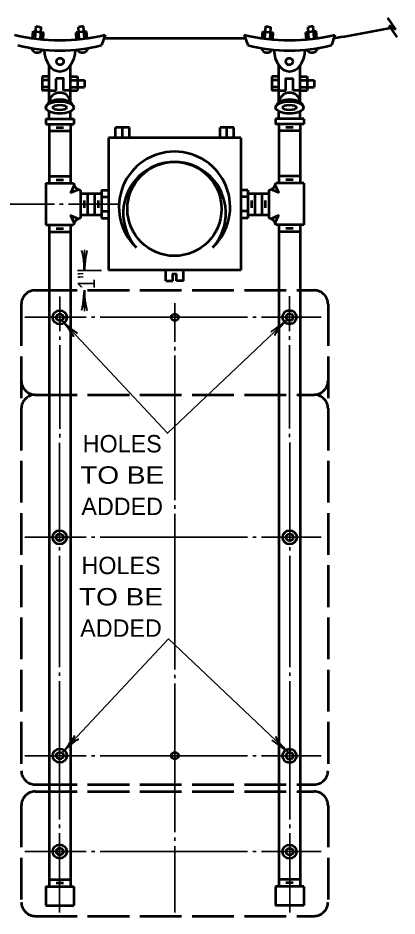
# Model space of a CAD drawing. Extents: x -35 to 821, y -10 to 534.
# Drawn here: x 188.7 to 253.9, y 232.6 to 387.3 of the extents above; entities that cross this region are included whole.
import ezdxf
from ezdxf.enums import TextEntityAlignment as Align

# ---------------------------------------------------------------- set-up
doc = ezdxf.new("R2010")
doc.units = 0
doc.header["$LTSCALE"] = 1.2
doc.linetypes.add('LONG_DASHED', pattern=[7.5, 6, -1.5])
doc.layers.add('1', color=7, linetype='Continuous', lineweight=35)

msp = doc.modelspace()

# ---------------------------------------------------------------- linework, layer by layer
at = {"layer": '1', "lineweight": 53}
for p, q in [((253.75, 385.374), (252.374, 387.34)), ((191.645, 383.84), (191.828, 385.932)), ((191.828, 385.932), (192.698, 385.763)), ((192.552, 383.668), (192.698, 385.763)), ((199.994, 385.898), (199.091, 385.76)), ((199.237, 383.665), (199.091, 385.76)), ((200.141, 383.803), (199.994, 385.898)), ((231.192, 383.803), (231.338, 385.898)), ((231.338, 385.898), (232.241, 385.76)), ((232.095, 383.665), (232.241, 385.76)), ((239.504, 385.932), (238.634, 385.763)), ((238.78, 383.668), (238.634, 385.763)), ((239.687, 383.84), (239.504, 385.932)), ((253.933, 384.055), (252.556, 386.021)), ((253.75, 385.374), (252.556, 386.021)), ((191.194, 383.851), (191.301, 385.075)), ((191.301, 385.075), (193.085, 384.834)), ((193.002, 383.649), (193.085, 384.834)), ((200.506, 385.031), (198.705, 384.831)), ((198.787, 383.649), (198.705, 384.831)), ((200.588, 383.85), (200.506, 385.031)), ((203.693, 384.427), (203.093, 382.627)), ((227.639, 384.427), (228.239, 382.627)), ((230.744, 383.85), (230.826, 385.031)), ((230.826, 385.031), (232.627, 384.831)), ((232.545, 383.649), (232.627, 384.831)), ((240.031, 385.075), (238.248, 384.834)), ((238.33, 383.649), (238.248, 384.834)), ((240.138, 383.851), (240.031, 385.075)), ((243.239, 384.427), (242.639, 382.627)), ((203.503, 383.857), (227.829, 383.857)), ((194.066, 372.783), (194.066, 379.155)), ((197.72, 372.783), (197.72, 379.155)), ((233.612, 372.783), (233.612, 379.155)), ((237.266, 372.783), (237.266, 379.155)), ((194.066, 377.227), (192.866, 377.227)), ((192.866, 377.227), (192.866, 374.827)), ((194.066, 376.627), (192.866, 376.627)), ((195.266, 374.827), (195.266, 376.927)), ((197.72, 377.227), (198.92, 377.227)), ((197.72, 376.627), (200.12, 376.627)), ((198.92, 377.227), (198.92, 374.827)), ((200.12, 376.627), (200.12, 375.427)), ((233.612, 377.227), (232.412, 377.227)), ((232.412, 377.227), (232.412, 374.827)), ((233.612, 376.627), (232.412, 376.627)), ((236.066, 374.827), (236.066, 376.927)), ((237.266, 377.227), (238.466, 377.227)), ((237.266, 376.627), (239.666, 376.627)), ((238.466, 377.227), (238.466, 374.827)), ((239.666, 376.627), (239.666, 375.427)), ((194.066, 375.427), (192.866, 375.427)), ((194.066, 374.827), (192.866, 374.827)), ((194.066, 374.827), (195.266, 374.827)), ((197.72, 374.827), (196.52, 374.827)), ((197.72, 375.427), (200.12, 375.427)), ((197.72, 374.827), (198.92, 374.827)), ((233.612, 375.427), (232.412, 375.427)), ((233.612, 374.827), (232.412, 374.827)), ((233.612, 374.827), (234.812, 374.827)), ((237.266, 374.827), (236.066, 374.827)), ((237.266, 375.427), (239.666, 375.427)), ((237.266, 374.827), (238.466, 374.827)), ((193.466, 369.958), (198.32, 369.958)), ((193.466, 369.958), (193.466, 369.058)), ((194.066, 369.958), (194.066, 371.227)), ((197.72, 369.958), (197.72, 371.227)), ((198.32, 369.958), (198.32, 369.058)), ((237.866, 369.958), (233.012, 369.958)), ((233.012, 369.958), (233.012, 369.058)), ((233.612, 369.958), (233.612, 371.227)), ((237.266, 369.958), (237.266, 371.227)), ((237.866, 369.958), (237.866, 369.058)), ((193.466, 369.058), (198.32, 369.058)), ((194.066, 369.058), (194.066, 358.858)), ((195.266, 368.458), (196.52, 368.458)), ((197.72, 369.058), (197.72, 358.858)), ((205.466, 366.685), (205.466, 368.485)), ((207.866, 368.485), (205.466, 368.485)), ((206.666, 366.685), (206.666, 368.485)), ((207.866, 366.685), (207.866, 368.485)), ((223.466, 366.685), (223.466, 368.485)), ((225.866, 368.485), (223.466, 368.485)), ((224.666, 366.685), (224.666, 368.485)), ((225.866, 366.685), (225.866, 368.485)), ((237.866, 369.058), (233.012, 369.058)), ((233.612, 369.058), (233.612, 358.858)), ((236.066, 368.458), (234.812, 368.458)), ((237.266, 369.058), (237.266, 358.858)), ((194.066, 367.858), (197.72, 367.858)), ((237.266, 367.858), (233.612, 367.858)), ((227.066, 366.685), (204.266, 366.685)), ((204.266, 366.685), (204.266, 343.843)), ((227.066, 366.685), (227.066, 343.843)), ((194.066, 360.058), (197.72, 360.058)), ((195.266, 359.458), (196.52, 359.458)), ((237.266, 360.058), (233.612, 360.058)), ((236.066, 359.458), (234.812, 359.458)), ((193.466, 358.858), (198.265, 358.858)), ((193.466, 358.858), (193.466, 351.658)), ((199.466, 357.685), (199.466, 352.83)), ((203.066, 357.685), (203.066, 352.843)), ((203.066, 357.685), (204.266, 357.685)), ((228.266, 357.685), (227.066, 357.685)), ((228.266, 357.685), (228.266, 352.843)), ((231.866, 357.685), (231.866, 352.83)), ((237.866, 358.858), (233.067, 358.858)), ((237.866, 358.858), (237.866, 351.658)), ((199.466, 357.084), (203.066, 357.084)), ((200.666, 357.084), (200.666, 353.43)), ((201.866, 357.084), (201.866, 353.43)), ((203.066, 356.485), (204.266, 356.485)), ((228.266, 356.485), (227.066, 356.485)), ((228.266, 357.084), (231.866, 357.084)), ((229.466, 357.084), (229.466, 353.43)), ((230.666, 357.084), (230.666, 353.43)), ((200.066, 355.885), (200.066, 354.63)), ((202.466, 355.885), (202.466, 354.63)), ((228.866, 355.885), (228.866, 354.63)), ((231.266, 355.885), (231.266, 354.63)), ((199.466, 353.43), (203.066, 353.43)), ((203.066, 354.043), (204.266, 354.043)), ((228.266, 354.043), (227.066, 354.043)), ((228.266, 353.43), (231.866, 353.43)), ((193.466, 351.658), (198.261, 351.658)), ((194.066, 351.658), (197.72, 351.658)), ((197.72, 351.658), (197.72, 340.407)), ((203.066, 352.843), (204.266, 352.843)), ((228.266, 352.843), (227.066, 352.843)), ((237.866, 351.658), (233.072, 351.658)), ((237.266, 351.658), (233.612, 351.658)), ((237.266, 351.658), (237.266, 306.058)), ((194.066, 350.458), (197.72, 350.458)), ((195.266, 351.058), (196.52, 351.058)), ((237.266, 350.458), (233.612, 350.458)), ((236.066, 351.058), (234.812, 351.058)), ((227.066, 343.843), (204.266, 343.843)), ((214.166, 342.043), (214.166, 343.843)), ((217.166, 342.043), (217.166, 343.843)), ((215.966, 342.043), (215.966, 343.243)), ((214.166, 342.043), (215.366, 342.043)), ((217.166, 342.043), (215.966, 342.043)), ((197.72, 340.407), (197.72, 255.207)), ((237.266, 306.058), (237.266, 237.657)), ((197.72, 255.207), (197.72, 237.657)), ((194.066, 238.858), (197.72, 238.858)), ((237.266, 238.858), (233.612, 238.858)), ((193.466, 237.657), (198.32, 237.657)), ((193.466, 237.657), (193.466, 234.358)), ((195.266, 238.258), (196.52, 238.258)), ((198.32, 237.657), (198.32, 234.358)), ((233.012, 237.657), (233.012, 234.358)), ((237.866, 237.657), (233.012, 237.657)), ((236.066, 238.258), (234.812, 238.258)), ((237.866, 237.657), (237.866, 234.358)), ((193.466, 234.358), (198.32, 234.358)), ((237.866, 234.358), (233.012, 234.358))]:
    msp.add_line(p, q, dxfattribs=at)
at = {"layer": '1'}
for p, q in [((194.966, 355.257), (176.639, 355.257)), ((195.866, 355.257), (196.466, 355.257)), ((197.366, 355.257), (206.086, 355.257)), ((200.12, 343.791), (200.12, 347.391)), ((198.92, 343.791), (203.066, 343.791)), ((195.893, 339.337), (195.893, 333.338)), ((200.12, 340.407), (200.12, 336.807)), ((235.439, 339.371), (235.439, 333.371)), ((215.666, 338.177), (215.666, 331.547)), ((189.866, 335.777), (200.42, 335.777)), ((199.82, 335.777), (200.42, 335.777)), ((201.32, 335.777), (201.92, 335.777)), ((202.82, 335.777), (228.212, 335.777)), ((229.112, 335.777), (229.712, 335.777)), ((230.612, 335.777), (240.866, 335.777)), ((195.893, 332.438), (195.893, 331.838)), ((235.439, 332.471), (235.439, 331.871)), ((195.893, 330.938), (195.893, 316.538)), ((215.666, 330.047), (215.666, 330.647)), ((235.439, 330.971), (235.439, 316.571)), ((215.666, 329.147), (215.666, 304.257)), ((195.893, 315.637), (195.893, 315.038)), ((235.439, 315.671), (235.439, 315.071)), ((195.865, 314.137), (195.865, 297.05)), ((235.467, 314.171), (235.467, 297.05)), ((215.666, 302.757), (215.666, 303.358)), ((215.666, 301.858), (215.666, 275.031)), ((189.866, 297.831), (200.42, 297.831)), ((201.32, 297.831), (201.92, 297.831)), ((202.82, 297.831), (228.212, 297.831)), ((229.112, 297.831), (229.712, 297.831)), ((240.866, 297.831), (230.612, 297.831)), ((240.866, 297.831), (231.266, 297.831)), ((195.865, 296.15), (195.865, 295.55)), ((235.467, 296.15), (235.467, 295.55)), ((195.865, 294.65), (195.865, 275.45)), ((235.467, 294.65), (235.467, 275.45)), ((195.865, 274.55), (195.865, 273.95)), ((215.666, 273.531), (215.666, 274.131)), ((235.467, 274.55), (235.467, 273.95)), ((195.865, 273.05), (195.865, 249.207)), ((215.666, 272.631), (215.666, 246.99)), ((235.467, 273.05), (235.467, 249.207)), ((189.866, 260.159), (200.42, 260.159)), ((201.32, 260.159), (201.92, 260.159)), ((202.82, 260.159), (228.212, 260.159)), ((229.112, 260.159), (229.712, 260.159)), ((230.612, 260.159), (240.866, 260.159)), ((215.666, 254.751), (215.666, 255.351)), ((195.865, 247.707), (195.865, 248.307)), ((235.467, 247.707), (235.467, 248.307)), ((195.865, 246.807), (195.865, 233.157)), ((235.467, 246.807), (235.467, 233.157)), ((215.666, 246.09), (215.666, 245.49)), ((215.666, 244.59), (215.666, 233.157)), ((189.866, 243.657), (200.42, 243.657)), ((201.32, 243.657), (201.92, 243.657)), ((202.82, 243.657), (228.212, 243.657)), ((229.112, 243.657), (229.712, 243.657)), ((230.612, 243.657), (240.866, 243.657))]:
    msp.add_line(p, q, dxfattribs=at)
at = {"layer": '1', "linetype": 'LONG_DASHED', "lineweight": 53}
for p, q in [((191.666, 340.407), (239.666, 340.407)), ((189.266, 338.007), (189.266, 320.007)), ((242.066, 338.007), (242.066, 320.007)), ((191.666, 322.407), (239.666, 322.407)), ((189.266, 320.007), (189.266, 257.607)), ((242.066, 320.007), (242.066, 257.607)), ((191.666, 255.207), (239.666, 255.207)), ((191.666, 254.007), (239.666, 254.007)), ((189.266, 251.607), (189.266, 234.952)), ((242.066, 251.607), (242.066, 234.952)), ((191.666, 232.552), (239.666, 232.552))]:
    msp.add_line(p, q, dxfattribs=at)
at = {"layer": '1', "lineweight": 13}
for p, q in [((215.666, 255.351), (215.666, 256.251)), ((215.666, 253.851), (215.666, 254.751))]:
    msp.add_line(p, q, dxfattribs=at)
at = {"layer": '1', "lineweight": 53}
for points in [[(196.52, 374.827), (196.52, 376.927), (195.266, 376.927)], [(234.812, 374.827), (234.812, 376.927), (236.066, 376.927)], [(198.359, 358.494), (197.777, 357.238), (199.087, 357.775)], [(232.974, 358.494), (233.555, 357.238), (232.246, 357.775)], [(198.354, 352.021), (197.772, 353.276), (199.082, 352.739)], [(232.978, 352.021), (233.56, 353.276), (232.25, 352.739)], [(194.066, 351.658), (194.066, 306.058), (194.066, 237.657)], [(233.612, 351.658), (233.612, 306.058), (233.612, 237.657)], [(215.366, 342.043), (215.366, 343.243), (215.966, 343.243)]]:
    msp.add_lwpolyline(points, dxfattribs=at)
at = {"layer": '1'}
for points in [[(196.23, 335.237), (214.413, 315.752), (235.041, 335.338)], [(196.426, 260.835), (214.61, 280.32), (235.237, 260.734)]]:
    msp.add_lwpolyline(points, dxfattribs=at)
at = {"layer": '1', "lineweight": 53}
for centre, radius in [((195.947, 379.834), 0.6), ((235.386, 379.834), 0.6), ((215.629, 354.421), 8.1), ((195.882, 335.737), 1.2), ((195.899, 335.737), 0.6), ((215.695, 335.747), 0.6), ((235.438, 335.771), 1.2), ((235.456, 335.771), 0.6), ((195.871, 297.824), 1.2), ((235.461, 297.824), 1.2), ((195.889, 297.824), 0.6), ((235.444, 297.824), 0.6), ((195.882, 260.199), 1.2), ((195.899, 260.199), 0.6), ((215.695, 260.19), 0.6), ((235.438, 260.165), 1.2), ((235.456, 260.165), 0.6), ((195.875, 243.674), 1.2), ((235.436, 243.646), 1.2), ((195.893, 243.674), 0.6), ((235.453, 243.646), 0.6)]:
    msp.add_circle(centre, radius, dxfattribs=at)
for centre, radius, start, end in [((192.406, 692.04), 312.316, 279.33196, 281.15709), ((195.893, 417.777), 34.25, 256.83593, 283.1638), ((235.439, 417.777), 34.25, 256.8362, 283.16407), ((195.893, 410.977), 29.25, 255.74997, 284.25003), ((235.439, 410.977), 29.25, 255.74997, 284.25003), ((192.007, 382.342), 0.986, 192.33045, 332.21364), ((199.783, 382.342), 0.986, 207.78636, 347.66955), ((231.55, 382.342), 0.986, 192.33045, 332.21364), ((239.326, 382.342), 0.986, 207.78636, 347.66955), ((195.893, 372.624), 1.834, 4.98578, 175.01422), ((235.439, 372.624), 1.834, 4.98578, 175.01422), ((215.641, 354.737), 9.57, 313.60282, 226.39718), ((215.641, 353.683), 8.837, 318.31863, 221.68137), ((199.581, 359.003), 1.324, 186.32364, 248.08344), ((199.581, 359.003), 1.324, 202.62687, 248.08262), ((199.581, 359.003), 1.324, 248.08344, 265.0377), ((231.752, 359.003), 1.324, 274.9623, 291.91656), ((231.752, 359.003), 1.324, 291.91656, 353.67636), ((231.752, 359.003), 1.324, 291.91738, 337.37313), ((199.576, 351.511), 1.324, 111.91656, 173.65459), ((199.576, 351.511), 1.324, 111.91738, 157.37313), ((199.576, 351.511), 1.324, 94.77118, 111.91656), ((231.756, 351.511), 1.324, 68.08344, 85.22882), ((231.756, 351.511), 1.324, 6.34541, 68.08344), ((231.756, 351.511), 1.324, 22.62687, 68.08262)]:
    msp.add_arc(centre, radius, start, end, dxfattribs=at)
at = {"layer": '1', "linetype": 'LONG_DASHED', "lineweight": 53}
for centre, start, end in [((191.666, 338.007), 90, 180), ((239.666, 338.007), 0, 90), ((191.666, 324.807), 180, 270), ((239.666, 324.807), 270, 0), ((191.666, 320.007), 90, 180), ((239.666, 320.007), 0, 90), ((191.666, 257.607), 180, 270), ((191.666, 257.607), 180, 270), ((239.666, 257.607), 270, 0), ((191.666, 251.607), 90, 180), ((239.666, 251.607), 0, 90), ((191.666, 234.952), 180, 270), ((239.666, 234.952), 270, 0)]:
    msp.add_arc(centre, 2.4, start, end, dxfattribs=at)
at = {"layer": '1', "lineweight": 53}
for centre, major_axis, ratio, start_param, end_param in [((195.893, 382.027), (0, 3.9), 0.692308, 1.615522, 4.6676498), ((235.439, 382.027), (0, 3.9), 0.692308, 1.6155355, 4.6676633), ((195.893, 371.908), (2.4, 0), 0.5625, 6.2831853, 9.424778), ((235.439, 371.908), (-2.4, 0), 0.5625, 3.1415927, 6.2831853)]:
    msp.add_ellipse(centre, major_axis=major_axis, ratio=ratio, start_param=start_param, end_param=end_param, dxfattribs=at)
for centre, major_axis, ratio in [((195.893, 371.908), (2.4, 0), 0.4375), ((195.893, 371.908), (1.2, 0), 0.375), ((235.439, 371.908), (-2.4, 0), 0.4375), ((235.439, 371.908), (-1.2, 0), 0.375)]:
    msp.add_ellipse(centre, major_axis=major_axis, ratio=ratio, dxfattribs=at)
at = {"layer": '1', "lineweight": 40}
for centre, major_axis, ratio, start_param, end_param in [((199.789, 345.1), (0.187, -2.143), 0.122415, 0.8963533, 3.1415927), ((200.374, 345.135), (-0.211, -2.108), 0.07063, 3.1407148, 5.41811), ((199.866, 339.062), (0.211, 2.108), 0.07063, 3.1407148, 5.41811), ((200.452, 339.097), (-0.187, 2.143), 0.122415, 0.8963533, 3.1415927), ((196.962, 334.081), (-1.284, 1.685), 0.07063, 3.1407148, 5.41811), ((196.962, 334.081), (-1.284, 1.685), 0.07063, 3.1407148, 5.41811), ((197.366, 334.506), (-1.599, 1.439), 0.122415, 0.8963533, 3.1415927), ((197.366, 334.506), (-1.599, 1.439), 0.122415, 0.8963533, 3.1415927), ((233.891, 334.596), (-1.674, -1.298), 0.07063, 6.2823074, 8.5597026), ((234.319, 334.196), (1.425, 1.611), 0.122415, 0.8963533, 3.1415927), ((197.158, 261.991), (-1.284, -1.685), 0.07063, 0.8650754, 3.1424706), ((197.158, 261.991), (-1.284, -1.685), 0.07063, 0.8650754, 3.1424706), ((234.516, 261.876), (1.425, -1.611), 0.122415, 3.1415927, 5.386832), ((197.562, 261.566), (-1.599, -1.439), 0.122415, 3.1415927, 5.386832), ((197.562, 261.566), (-1.599, -1.439), 0.122415, 3.1415927, 5.386832), ((234.087, 261.476), (-1.674, 1.298), 0.07063, 4.006668, 6.2840632)]:
    msp.add_ellipse(centre, major_axis=major_axis, ratio=ratio, start_param=start_param, end_param=end_param, dxfattribs=at)

# ---------------------------------------------------------------- texts
at = {"layer": '1', "width": 0.8}
msp.add_text('1"', height=3, rotation=90, dxfattribs=at).set_placement((201.976, 340.615))
at = {"layer": '1'}
for s, p in [('HOLES', (206.63, 312.459)), ('ADDED', (206.63, 301.66)), ('HOLES', (206.425, 291.479)), ('ADDED', (206.425, 280.679))]:
    msp.add_text(s, height=3, dxfattribs=at).set_placement(p, align=Align.CENTER)
at = {"layer": '1', "width": 1.2}
for p in [(206.63, 307.06), (206.425, 286.079)]:
    msp.add_text('TO BE', height=3, dxfattribs=at).set_placement(p, align=Align.CENTER)

doc.saveas('drawing.dxf')
